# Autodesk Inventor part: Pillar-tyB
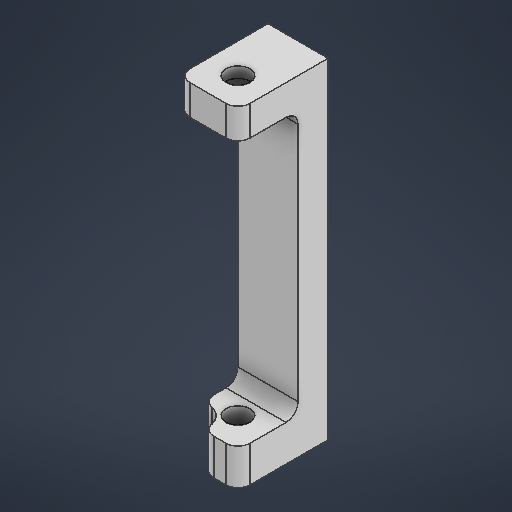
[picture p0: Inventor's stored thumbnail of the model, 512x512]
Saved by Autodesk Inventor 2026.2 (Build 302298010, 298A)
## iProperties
Created: 2026-05
Part Number: Pillar-tyB
Material: 일반
Document SubType Name: Modeling
Designer: work
Density: 1 g/cm^3
Appearance: 기본값
Author: work
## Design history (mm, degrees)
sketch "스케치1"
  geometry: L1 (-5, 5)-(5, 5); L2 (5, 5)-(5, -5); L3 (5, -5)-(-5, -5); L4 (-5, -5)-(-5, 5); L5 (-5, 5)-(5, -5); L6 (5, 5)-(-5, -5); L7 (5, -5)-(-5, -5); L8 (-5, -5)-(-5, -11); L9 (-5, -11)-(5, -11); L10 (5, -11)-(5, -5); C1 r 2 at (0, 0); C2 r 3.1 at (4, 4); 3 further points
  constraints: 20 end point, 4 parallel, 2 centre point, 2 horizontal, 2 midpoint, 2 perpendicular, 1 coincident
  dimensions: "d0" = 4 diameter of C1; "d1" = 10 distance of L2.end L3.end; "d2" = 10 distance of L1.end L2.end; "d3" = 6 distance of L9.end L2.end; "d4" = 6.2 diameter of C2; "d5" = 4 horizontal distance of point (0, 0) C2.centre; "d6" = 4 horizontal distance of C2.centre point (0, 0)
extrude "돌출1" new body sketch "스케치1" distance "d7" = 6; taper "d8" = 0 deg
extrude "돌출2" join sketch "스케치1" distance "d9" = 50; taper "d10" = 0 deg
sketch "스케치2"
  geometry: L1 (5, 5)-(-5, 5) reference; L2 (-5, 5)-(-5, -1.066) reference; L3 (-1.066, -5)-(5, -5) reference; L4 (5, -5)-(5, 5) reference; L5 (-5, 5)-(5, 5) reference; L6 (5, 5)-(5, 11) reference; L7 (5, 11)-(-5, 11) reference; L8 (-5, 11)-(-5, 5) reference; L9 (-5, -1.066)-(-5, -5); L10 (-5, -5)-(-1.066, -5); C1 r 2 at (0, 0) reference; A1 r 3.1 centre (-4, -4) between (-1.066, -5) and (-5, -1.066) reference; 3 further points
  constraints: 4 end point, 1 perpendicular, 1 vertical
extrude "돌출3" join sketch "스케치2" distance "d11" = 5; taper "d12" = 0 deg
sketch "스케치3"
  geometry: C1 r 2 at (0, 0) reference; 2 further points
  constraints: 1 coincident
hole "구멍1" sketch "스케치3" at (0, 0) diameter "d13" = 4; stored, may be unused: countersink angle "d17" = 90 deg, drill point angle "d19" = 118 deg; dims "d14" = 6, "d15" = 6.2, "d16" = 3.2, "d18" = 8
fillet "모깎기1" dims "d20" = 2
chamfer "모따기1" distance "d21" = 1; stored, may be unused: second distance "d22" = 2, angle "d23" = 45 deg
node "솔리드1"
node "투영된 루프1"
node "투영된 루프2"
feature "A9D066F2-1C7D-4E18-AEED-F7BC21143FA4" dims "d13" = 4, "d14" = 6, "d15" = 6.2, "d16" = 3.2, "d17" = 90 deg, "d18" = 8, "d19" = 118 deg
